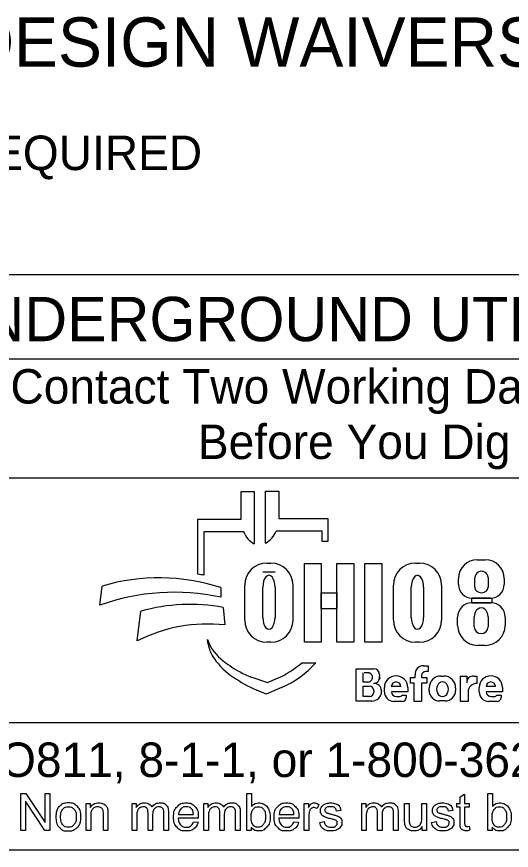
# Model space of a CAD drawing. Extents: x 0 to 34, y 0 to 22.
# Drawn here: x 2.822 to 4.831, y 2.143 to 5.529 of the extents above; entities that cross this region are included whole.
import ezdxf

# ---------------------------------------------------------------- set-up
doc = ezdxf.new("R2010")
doc.units = 0
doc.layers.add('SC_Scratch9', color=7, linetype='Continuous')
doc.layers.add('SH_Cut_Line', color=7, linetype='Continuous')

msp = doc.modelspace()

# ---------------------------------------------------------------- linework, layer by layer
at = {"layer": 'SC_Scratch9'}
for p, q in [((3.7335, 3.4883), (3.7335, 3.5998)), ((3.7335, 3.5998), (3.7872, 3.5998)), ((3.7872, 3.5998), (3.7872, 3.3877)), ((3.8329, 3.39), (3.8329, 3.6021)), ((3.8329, 3.6021), (3.8865, 3.6021)), ((3.8865, 3.6021), (3.8865, 3.4906)), ((3.5576, 3.2644), (3.5576, 3.4883)), ((3.5576, 3.4883), (3.7335, 3.4883)), ((3.8865, 3.4906), (4.0857, 3.4906)), ((4.0857, 3.4906), (4.0857, 3.3968)), ((3.5828, 3.4369), (3.5828, 3.26)), ((3.7439, 3.4369), (3.5828, 3.4369)), ((4.0625, 3.4392), (3.8761, 3.4392)), ((4.0625, 3.3968), (4.0625, 3.4392)), ((4.0857, 3.3968), (4.0625, 3.3968)), ((4.6931, 3.3231), (4.7258, 3.3231)), ((3.8385, 3.3091), (3.8551, 3.3091)), ((4.4416, 3.3091), (4.4581, 3.3091)), ((3.8718, 3.2721), (3.822, 3.2721)), ((4.683, 3.2111), (4.683, 3.2504)), ((4.7371, 3.2504), (4.7371, 3.2111)), ((3.7491, 3.0776), (3.7491, 3.2196)), ((3.9445, 3.2196), (3.9445, 3.0776)), ((4.3521, 3.0776), (4.3521, 3.2196)), ((4.5476, 3.2196), (4.5476, 3.0776)), ((4.6168, 3.2225), (4.6168, 3.2468)), ((4.8022, 3.2468), (4.8022, 3.2225)), ((3.1602, 3.1381), (3.1696, 3.2162)), ((3.6509, 3.2097), (3.6509, 3.1709)), ((3.822, 3.089), (3.822, 3.2114)), ((3.8718, 3.2114), (3.8718, 3.089)), ((4.425, 3.089), (4.425, 3.2114)), ((4.4748, 3.2114), (4.4748, 3.089)), ((4.7462, 3.1665), (4.6728, 3.1665)), ((3.6608, 3.1291), (3.6671, 3.0582)), ((4.671, 3.1482), (4.7483, 3.1482)), ((3.312, 2.9936), (3.3267, 3.1137)), ((4.6131, 3.0563), (4.6131, 3.0903)), ((4.6806, 3.0503), (4.6806, 3.0912)), ((4.7374, 3.0912), (4.7374, 3.0503)), ((4.8062, 3.0903), (4.8062, 3.0563)), ((3.5997, 2.9807), (3.5967, 2.9986)), ((3.8551, 2.9882), (3.8385, 2.9882)), ((4.4581, 2.9882), (4.4416, 2.9882)), ((4.7252, 2.9753), (4.6941, 2.9753)), ((3.98, 2.9048), (4.0375, 2.9048)), ((4.2013, 2.749), (4.2013, 2.8798)), ((4.2013, 2.8798), (4.2725, 2.8798)), ((4.4739, 2.8926), (4.4934, 2.8926)), ((4.4934, 2.8926), (4.4934, 2.8696)), ((3.7816, 2.8444), (3.841, 2.8239)), ((4.2293, 2.8263), (4.2293, 2.8632)), ((4.2545, 2.8632), (4.2332, 2.8632)), ((4.2963, 2.856), (4.2963, 2.8481)), ((4.4213, 2.8212), (4.4213, 2.8442)), ((4.4213, 2.8442), (4.4406, 2.8442)), ((4.4406, 2.8442), (4.4406, 2.8546)), ((4.4667, 2.8526), (4.4667, 2.8442)), ((4.4667, 2.8442), (4.4883, 2.8442)), ((4.4934, 2.8691), (4.4832, 2.8691)), ((4.4883, 2.8442), (4.4883, 2.8212)), ((4.5451, 2.8508), (4.5573, 2.8508)), ((4.6254, 2.7478), (4.6254, 2.8505)), ((4.6254, 2.8505), (4.6499, 2.8505)), ((4.6499, 2.8505), (4.6499, 2.8237)), ((4.6772, 2.8505), (4.691, 2.8505)), ((4.691, 2.8505), (4.691, 2.8209)), ((3.841, 2.8239), (3.8821, 2.8417)), ((4.2487, 2.8263), (4.2293, 2.8263)), ((4.4362, 2.8212), (4.4213, 2.8212)), ((4.4362, 2.7478), (4.4362, 2.8212)), ((4.4883, 2.8212), (4.4667, 2.8212)), ((4.4667, 2.8212), (4.4667, 2.7478)), ((3.835, 2.7769), (3.7976, 2.7934)), ((3.8983, 2.8044), (3.835, 2.7769)), ((4.2293, 2.7669), (4.2293, 2.8097)), ((4.2293, 2.8097), (4.2548, 2.8097)), ((4.2729, 2.7916), (4.2729, 2.7853)), ((4.3043, 2.7887), (4.3043, 2.7884)), ((4.3159, 2.7858), (4.3159, 2.8042)), ((4.3824, 2.8082), (4.3439, 2.8082)), ((4.4104, 2.7866), (4.344, 2.7866)), ((4.4104, 2.8042), (4.4104, 2.7866)), ((4.4973, 2.7922), (4.4973, 2.8029)), ((4.6051, 2.8029), (4.6051, 2.7922)), ((4.6559, 2.786), (4.6559, 2.7478)), ((4.7008, 2.7858), (4.7008, 2.8042)), ((4.7674, 2.8082), (4.7288, 2.8082)), ((4.7953, 2.7866), (4.7289, 2.7866)), ((4.7953, 2.8042), (4.7953, 2.7866)), ((4.265, 2.749), (4.2013, 2.749)), ((4.2546, 2.7669), (4.2293, 2.7669)), ((4.3892, 2.7478), (4.3538, 2.7478)), ((4.3649, 2.7673), (4.379, 2.7673)), ((4.3876, 2.7729), (4.4045, 2.7729)), ((4.4045, 2.7729), (4.4045, 2.7631)), ((4.4667, 2.7478), (4.4362, 2.7478)), ((4.5623, 2.7494), (4.5401, 2.7494)), ((4.6559, 2.7478), (4.6254, 2.7478)), ((4.7742, 2.7478), (4.7388, 2.7478)), ((4.7498, 2.7673), (4.7639, 2.7673)), ((4.7725, 2.7729), (4.7894, 2.7729)), ((4.7894, 2.7729), (4.7894, 2.7631))]:
    msp.add_line(p, q, dxfattribs=at)
for points in [[(3.991, 3.3081), (4.0589, 3.3081), (4.0589, 2.9881), (3.991, 2.9881)], [(4.1231, 3.3081), (4.1911, 3.3081), (4.1911, 2.9881), (4.1231, 2.9881)], [(4.2364, 3.3081), (4.3052, 3.3081), (4.3052, 2.9881), (4.2364, 2.9881)], [(4.0589, 3.1882), (4.1231, 3.1882), (4.1231, 3.1242), (4.0589, 3.1242)], [(4.6706, 3.1665), (4.7523, 3.1665), (4.7523, 3.1481), (4.6706, 3.1481)]]:
    msp.add_lwpolyline(points, close=True, dxfattribs=at)
for points in [[(2.8389, 2.2239), (2.8389, 2.3741), (2.8592, 2.3741), (2.9382, 2.2561), (2.9382, 2.3741), (2.9572, 2.3741), (2.9572, 2.2239), (2.9369, 2.2239), (2.8579, 2.3419), (2.8579, 2.2239), (2.8389, 2.2239)], [(3.7743, 2.2239), (3.7573, 2.2239), (3.7573, 2.3741), (3.7757, 2.3741), (3.7757, 2.3206)], [(4.6233, 2.2558), (4.6233, 2.3185), (4.6097, 2.3185), (4.6097, 2.3328), (4.6233, 2.3328), (4.6233, 2.3597), (4.6417, 2.3708), (4.6417, 2.3328), (4.6601, 2.3328), (4.6601, 2.3185), (4.6417, 2.3185), (4.6417, 2.2547)], [(4.7534, 2.2239), (4.7363, 2.2239), (4.7363, 2.3741), (4.7548, 2.3741), (4.7548, 2.3206)], [(3.1048, 2.2239), (3.1048, 2.3328), (3.1214, 2.3328), (3.1214, 2.3173)], [(3.2912, 2.2239), (3.2912, 2.3328), (3.3077, 2.3328), (3.3077, 2.3174)], [(3.5826, 2.2239), (3.5826, 2.3328), (3.5991, 2.3328), (3.5991, 2.3174)], [(3.9904, 2.2239), (3.9904, 2.3328), (4.007, 2.3328), (4.007, 2.3163)], [(4.0495, 2.3293), (4.043, 2.3122)], [(4.1394, 2.3046), (4.1213, 2.3022)], [(4.2236, 2.2239), (4.2236, 2.3328), (4.2401, 2.3328), (4.2401, 2.3174)], [(4.3979, 2.2654), (4.3979, 2.3328), (4.4164, 2.3328), (4.4164, 2.2724)], [(4.4676, 2.2745), (4.4676, 2.3328), (4.4861, 2.3328), (4.4861, 2.2239), (4.4696, 2.2239)], [(4.594, 2.3046), (4.5759, 2.3022)], [(3.1233, 2.2833), (3.1233, 2.2239), (3.1048, 2.2239)], [(3.1932, 2.2908), (3.1932, 2.2239), (3.1748, 2.2239), (3.1748, 2.2901)], [(3.3097, 2.2803), (3.3097, 2.2239), (3.2912, 2.2239)], [(3.3743, 2.2871), (3.3743, 2.2239), (3.3559, 2.2239), (3.3559, 2.2946)], [(3.4388, 2.2986), (3.4388, 2.2239), (3.4203, 2.2239), (3.4203, 2.2924)], [(3.56, 2.2736), (3.4788, 2.2736)], [(3.4799, 2.2887), (3.5406, 2.2887)], [(3.601, 2.2803), (3.601, 2.2239), (3.5826, 2.2239)], [(3.6657, 2.2871), (3.6657, 2.2239), (3.6473, 2.2239), (3.6473, 2.2946)], [(3.7301, 2.2986), (3.7301, 2.2239), (3.7117, 2.2239), (3.7117, 2.2924)], [(3.968, 2.2736), (3.8868, 2.2736)], [(3.8879, 2.2887), (3.9486, 2.2887)], [(4.0088, 2.2809), (4.0088, 2.2239), (3.9904, 2.2239)], [(4.242, 2.2803), (4.242, 2.2239), (4.2236, 2.2239)], [(4.3067, 2.2871), (4.3067, 2.2239), (4.2883, 2.2239), (4.2883, 2.2946)], [(4.3711, 2.2986), (4.3711, 2.2239), (4.3527, 2.2239), (4.3527, 2.2924)], [(3.5404, 2.2591), (3.5595, 2.2567)], [(3.7743, 2.2375), (3.7743, 2.2239)], [(3.9484, 2.2591), (3.9675, 2.2567)], [(4.053, 2.2564), (4.0712, 2.2593)], [(4.4696, 2.2239), (4.4696, 2.24)], [(4.5076, 2.2564), (4.5258, 2.2593)], [(4.6601, 2.2404), (4.6628, 2.2241)], [(4.7534, 2.2375), (4.7534, 2.2239)]]:
    msp.add_lwpolyline(points, dxfattribs=at)
for centre, radius, start, end in [((3.8353, 3.4736), 0.0985, 201.9296, 240.7469), ((3.7847, 3.476), 0.0985, 299.2531, 338.0704), ((4.6931, 3.2468), 0.0763, 90, 180), ((4.7258, 3.2468), 0.0763, 0, 90), ((3.8385, 3.2196), 0.0895, 90, 180), ((3.8551, 3.2196), 0.0895, 0, 90), ((4.4416, 3.2196), 0.0895, 90, 180), ((4.4581, 3.2196), 0.0895, 0, 90), ((3.4295, 2.4554), 0.8191, 79.2074, 81.0007), ((3.3997, 2.4302), 0.8191, 72.1402, 106.3144), ((4.6728, 3.2225), 0.056, 180, 270), ((4.7462, 3.2225), 0.056, 270, 0), ((3.4628, 2.2991), 0.8919, 77.8238, 109.8274), ((3.5267, 2.4094), 0.7322, 79.44, 105.8467), ((4.671, 3.0903), 0.0579, 90, 180), ((4.7483, 3.0903), 0.0579, 0, 90), ((3.5987, 2.4262), 0.6357, 83.8248, 116.8021), ((3.8385, 3.0776), 0.0895, 180, 270), ((3.8551, 3.0776), 0.0895, 270, 0), ((4.4416, 3.0776), 0.0895, 180, 270), ((4.4581, 3.0776), 0.0895, 270, 0), ((4.6941, 3.0563), 0.081, 180, 270), ((4.7252, 3.0563), 0.081, 270, 0), ((3.7841, 3.0707), 0.2008, 201.0457, 232.5314), ((3.741, 3.0048), 0.1433, 189.6817, 216.0884), ((3.8747, 3.1022), 0.3088, 216.0884, 235.7167), ((3.9766, 3.3219), 0.5173, 232.5314, 241.794), ((3.7387, 3.1722), 0.3602, 293.4582, 312.0712), ((3.7387, 3.1722), 0.401, 293.4582, 317.8286), ((4.2725, 2.856), 0.0238, 0, 90), ((4.4739, 2.859), 0.0335, 90, 187.5187), ((4.0412, 3.3465), 0.6044, 235.7167, 246.2325), ((3.8914, 3.1631), 0.3371, 241.794, 250.9821), ((4.2487, 2.845), 0.0187, 270, 2.0582), ((4.2505, 2.8463), 0.0169, 357.8325, 90), ((4.2721, 2.8453), 0.0243, 270, 6.6529), ((4.3631, 2.8042), 0.0473, 0, 180), ((4.4832, 2.8526), 0.0165, 90, 180), ((4.5451, 2.8029), 0.0478, 90, 180), ((4.5573, 2.8029), 0.0478, 0, 90), ((4.6768, 2.8237), 0.0269, 89.2449, 180), ((4.7481, 2.8042), 0.0473, 0, 180), ((4.2722, 2.7889), 0.0321, 4.0748, 90), ((4.2827, 2.8438), 0.0175, 347.4023, 0), ((4.3632, 2.8072), 0.0193, 2.9632, 177.0368), ((4.6908, 2.786), 0.0349, 89.6033, 180), ((4.7481, 2.8072), 0.0193, 2.9632, 177.0368), ((4.2546, 2.7853), 0.0184, 270, 0), ((4.2548, 2.7916), 0.0181, 0, 90), ((4.265, 2.7884), 0.0393, 270, 0), ((4.2714, 2.7887), 0.033, 0, 11.7502), ((4.3538, 2.7858), 0.038, 180, 270), ((4.3649, 2.7883), 0.021, 184.827, 270), ((4.5401, 2.7922), 0.0428, 180, 270), ((4.5623, 2.7922), 0.0428, 270, 0), ((4.7388, 2.7858), 0.038, 180, 270), ((4.7498, 2.7883), 0.021, 184.827, 270), ((4.379, 2.7767), 0.00938, 270, 335.9979), ((4.3892, 2.7631), 0.0152, 270, 0), ((4.7639, 2.7767), 0.00938, 270, 335.9979), ((4.7742, 2.7631), 0.0152, 270, 0)]:
    msp.add_arc(centre, radius, start, end, dxfattribs=at)
for centre, major_axis, ratio, start_param, end_param in [((3.8469, 3.2114), (0, 0.0484), 0.514403, 4.712389, 7.853982), ((4.4499, 3.2114), (0, 0.0484), 0.514403, 4.712389, 7.853982), ((4.71, 3.2504), (0.0271, 0), 0.969373, 0, 3.141593), ((4.71, 3.2111), (0.0271, 0), 0.818453, 3.141593, 6.283185), ((4.709, 3.0912), (0, 0.0358), 0.794529, 4.712389, 7.853982), ((3.8469, 3.089), (0, 0.0484), 0.514403, 1.570796, 4.712389), ((4.4499, 3.089), (0, 0.0484), 0.514403, 1.570796, 4.712389), ((4.709, 3.0503), (0.0284, 0), 0.959837, 3.141593, 6.283185), ((4.5517, 2.7976), (0, 0.029), 0.832186, 4.712389, 7.853982), ((4.5517, 2.7976), (0, 0.0302), 0.797287, 1.570796, 4.712389)]:
    msp.add_ellipse(centre, major_axis=major_axis, ratio=ratio, start_param=start_param, end_param=end_param, dxfattribs=at)
for points in [[(2.9814, 2.2783), (2.9814, 2.3085), (2.9981, 2.3231), (3.0122, 2.3352), (3.0323, 2.3352), (3.0547, 2.3352), (3.069, 2.3205), (3.0832, 2.3058), (3.0832, 2.2799), (3.0832, 2.2589), (3.0769, 2.2469), (3.0706, 2.2348), (3.0586, 2.2282), (3.0466, 2.2215), (3.0323, 2.2215), (3.0095, 2.2215), (2.9954, 2.2362), (2.9814, 2.2508), (2.9814, 2.2783)], [(3.0003, 2.2783), (3.0003, 2.2574), (3.0094, 2.247), (3.0185, 2.2366), (3.0323, 2.2366), (3.046, 2.2366), (3.0551, 2.2471), (3.0642, 2.2575), (3.0642, 2.279), (3.0642, 2.2991), (3.0551, 2.3095), (3.0459, 2.3199), (3.0323, 2.3199), (3.0185, 2.3199), (3.0094, 2.3096), (3.0003, 2.2992), (3.0003, 2.2783)], [(3.1214, 2.3173), (3.1334, 2.3352), (3.156, 2.3352), (3.1659, 2.3352), (3.1741, 2.3316), (3.1823, 2.3281), (3.1864, 2.3224), (3.1905, 2.3166), (3.1922, 2.3087), (3.1932, 2.3036), (3.1932, 2.2908)], [(3.1748, 2.2901), (3.1748, 2.3013), (3.1726, 2.3069), (3.1705, 2.3125), (3.165, 2.3158), (3.1595, 2.3191), (3.1521, 2.3191), (3.1404, 2.3191), (3.1318, 2.3117), (3.1233, 2.3042), (3.1233, 2.2833)], [(3.3077, 2.3174), (3.3128, 2.3254), (3.3214, 2.3303), (3.3299, 2.3352), (3.3407, 2.3352), (3.3528, 2.3352), (3.3606, 2.3301), (3.3683, 2.3251), (3.3715, 2.3161), (3.3844, 2.3352), (3.4051, 2.3352), (3.4213, 2.3352), (3.43, 2.3262), (3.4388, 2.3172), (3.4388, 2.2986)], [(3.3559, 2.2946), (3.3559, 2.3069), (3.3514, 2.313), (3.3469, 2.3191), (3.3366, 2.3191), (3.3288, 2.3191), (3.3222, 2.315), (3.3156, 2.311), (3.3126, 2.3031), (3.3097, 2.2952), (3.3097, 2.2803)], [(3.4203, 2.2924), (3.4203, 2.3035), (3.4185, 2.3083), (3.4168, 2.3132), (3.412, 2.3162), (3.4073, 2.3191), (3.401, 2.3191), (3.3895, 2.3191), (3.3819, 2.3115), (3.3743, 2.3039), (3.3743, 2.2871)], [(3.5595, 2.2567), (3.555, 2.24), (3.5428, 2.2307), (3.5306, 2.2215), (3.5117, 2.2215), (3.4878, 2.2215), (3.4738, 2.2362), (3.4598, 2.2509), (3.4598, 2.2774), (3.4598, 2.3049), (3.474, 2.32), (3.4881, 2.3352), (3.5106, 2.3352), (3.5324, 2.3352), (3.5463, 2.3203), (3.5601, 2.3055), (3.5601, 2.2785), (3.5601, 2.2769), (3.56, 2.2736)], [(3.5406, 2.2887), (3.5394, 2.3025), (3.5337, 2.3094), (3.5249, 2.3201), (3.5108, 2.3201), (3.4981, 2.3201), (3.4894, 2.3115), (3.4808, 2.303), (3.4799, 2.2887)], [(3.5991, 2.3174), (3.6042, 2.3254), (3.6127, 2.3303), (3.6212, 2.3352), (3.6321, 2.3352), (3.6442, 2.3352), (3.6519, 2.3301), (3.6597, 2.3251), (3.6628, 2.3161), (3.6758, 2.3352), (3.6965, 2.3352), (3.7127, 2.3352), (3.7214, 2.3262), (3.7301, 2.3172), (3.7301, 2.2986)], [(3.6473, 2.2946), (3.6473, 2.3069), (3.6428, 2.313), (3.6383, 2.3191), (3.628, 2.3191), (3.6202, 2.3191), (3.6136, 2.315), (3.607, 2.311), (3.604, 2.3031), (3.601, 2.2952), (3.601, 2.2803)], [(3.7117, 2.2924), (3.7117, 2.3035), (3.7099, 2.3083), (3.7081, 2.3132), (3.7034, 2.3162), (3.6987, 2.3191), (3.6923, 2.3191), (3.6809, 2.3191), (3.6733, 2.3115), (3.6657, 2.3039), (3.6657, 2.2871)], [(3.7741, 2.2792), (3.7741, 2.2596), (3.7794, 2.2509), (3.7881, 2.2366), (3.8029, 2.2366), (3.815, 2.2366), (3.8238, 2.2471), (3.8326, 2.2576), (3.8326, 2.2784), (3.8326, 2.2998), (3.8241, 2.3099), (3.8157, 2.3201), (3.8038, 2.3201), (3.7917, 2.3201), (3.7829, 2.3096), (3.7741, 2.299), (3.7741, 2.2792)], [(3.7757, 2.3206), (3.7874, 2.3352), (3.8055, 2.3352), (3.8155, 2.3352), (3.8245, 2.3311), (3.8335, 2.3271), (3.8392, 2.3198), (3.845, 2.3124), (3.8483, 2.3021), (3.8516, 2.2918), (3.8516, 2.28), (3.8516, 2.252), (3.8378, 2.2368), (3.8239, 2.2215), (3.8046, 2.2215), (3.7853, 2.2215), (3.7743, 2.2375)], [(3.9675, 2.2567), (3.963, 2.24), (3.9508, 2.2307), (3.9386, 2.2215), (3.9196, 2.2215), (3.8958, 2.2215), (3.8818, 2.2362), (3.8678, 2.2509), (3.8678, 2.2774), (3.8678, 2.3049), (3.882, 2.32), (3.8961, 2.3352), (3.9186, 2.3352), (3.9404, 2.3352), (3.9543, 2.3203), (3.9681, 2.3055), (3.9681, 2.2785), (3.9681, 2.2769), (3.968, 2.2736)], [(3.9486, 2.2887), (3.9474, 2.3025), (3.9417, 2.3094), (3.9328, 2.3201), (3.9188, 2.3201), (3.9061, 2.3201), (3.8974, 2.3115), (3.8888, 2.303), (3.8879, 2.2887)], [(4.007, 2.3163), (4.0133, 2.3278), (4.0187, 2.3315), (4.0241, 2.3352), (4.0305, 2.3352), (4.0398, 2.3352), (4.0495, 2.3293)], [(4.043, 2.3122), (4.0363, 2.3162), (4.0295, 2.3162), (4.0235, 2.3162), (4.0187, 2.3125), (4.0139, 2.3089), (4.0119, 2.3024), (4.0088, 2.2926), (4.0088, 2.2809)], [(4.1213, 2.3022), (4.1201, 2.3106), (4.1142, 2.3153), (4.1083, 2.3201), (4.0975, 2.3201), (4.0848, 2.3201), (4.0794, 2.3159), (4.0739, 2.3116), (4.0739, 2.306), (4.0739, 2.3024), (4.0762, 2.2995), (4.0785, 2.2966), (4.0833, 2.2946), (4.086, 2.2936), (4.0996, 2.2899), (4.1192, 2.2847), (4.1269, 2.2813), (4.1347, 2.278), (4.1391, 2.2717), (4.1435, 2.2653), (4.1435, 2.2559), (4.1435, 2.2467), (4.1381, 2.2386), (4.1327, 2.2304), (4.1226, 2.226), (4.1124, 2.2215), (4.0996, 2.2215), (4.0784, 2.2215), (4.0672, 2.2303), (4.0561, 2.2391), (4.053, 2.2564)], [(4.0712, 2.2593), (4.0727, 2.2483), (4.0798, 2.2425), (4.0868, 2.2366), (4.0995, 2.2366), (4.1122, 2.2366), (4.1184, 2.2418), (4.1245, 2.247), (4.1245, 2.254), (4.1245, 2.2602), (4.1191, 2.2638), (4.1153, 2.2663), (4.1002, 2.2701), (4.0799, 2.2752), (4.072, 2.2789), (4.0642, 2.2827), (4.0601, 2.2893), (4.0561, 2.2959), (4.0561, 2.3038), (4.0561, 2.3111), (4.0594, 2.3173), (4.0628, 2.3235), (4.0685, 2.3276), (4.0728, 2.3308), (4.0803, 2.333), (4.0877, 2.3352), (4.0962, 2.3352), (4.109, 2.3352), (4.1187, 2.3315), (4.1284, 2.3278), (4.133, 2.3215), (4.1377, 2.3152), (4.1394, 2.3046)], [(4.2401, 2.3174), (4.2452, 2.3254), (4.2537, 2.3303), (4.2622, 2.3352), (4.2731, 2.3352), (4.2852, 2.3352), (4.2929, 2.3301), (4.3007, 2.3251), (4.3038, 2.3161), (4.3168, 2.3352), (4.3375, 2.3352), (4.3537, 2.3352), (4.3624, 2.3262), (4.3711, 2.3172), (4.3711, 2.2986)], [(4.2883, 2.2946), (4.2883, 2.3069), (4.2838, 2.313), (4.2793, 2.3191), (4.269, 2.3191), (4.2612, 2.3191), (4.2546, 2.315), (4.248, 2.311), (4.245, 2.3031), (4.242, 2.2952), (4.242, 2.2803)], [(4.3527, 2.2924), (4.3527, 2.3035), (4.3509, 2.3083), (4.3491, 2.3132), (4.3444, 2.3162), (4.3397, 2.3191), (4.3333, 2.3191), (4.3219, 2.3191), (4.3143, 2.3115), (4.3067, 2.3039), (4.3067, 2.2871)], [(4.5759, 2.3022), (4.5747, 2.3106), (4.5688, 2.3153), (4.5629, 2.3201), (4.5521, 2.3201), (4.5394, 2.3201), (4.5339, 2.3159), (4.5285, 2.3116), (4.5285, 2.306), (4.5285, 2.3024), (4.5308, 2.2995), (4.533, 2.2966), (4.5378, 2.2946), (4.5406, 2.2936), (4.5542, 2.2899), (4.5737, 2.2847), (4.5815, 2.2813), (4.5893, 2.278), (4.5937, 2.2717), (4.5981, 2.2653), (4.5981, 2.2559), (4.5981, 2.2467), (4.5927, 2.2386), (4.5873, 2.2304), (4.5772, 2.226), (4.567, 2.2215), (4.5542, 2.2215), (4.5329, 2.2215), (4.5218, 2.2303), (4.5107, 2.2391), (4.5076, 2.2564)], [(4.5258, 2.2593), (4.5273, 2.2483), (4.5343, 2.2425), (4.5414, 2.2366), (4.554, 2.2366), (4.5668, 2.2366), (4.5729, 2.2418), (4.5791, 2.247), (4.5791, 2.254), (4.5791, 2.2602), (4.5736, 2.2638), (4.5698, 2.2663), (4.5548, 2.2701), (4.5345, 2.2752), (4.5266, 2.2789), (4.5188, 2.2827), (4.5147, 2.2893), (4.5107, 2.2959), (4.5107, 2.3038), (4.5107, 2.3111), (4.514, 2.3173), (4.5173, 2.3235), (4.5231, 2.3276), (4.5274, 2.3308), (4.5348, 2.333), (4.5423, 2.3352), (4.5508, 2.3352), (4.5636, 2.3352), (4.5733, 2.3315), (4.583, 2.3278), (4.5876, 2.3215), (4.5922, 2.3152), (4.594, 2.3046)], [(4.7532, 2.2792), (4.7532, 2.2596), (4.7585, 2.2509), (4.7672, 2.2366), (4.782, 2.2366), (4.7941, 2.2366), (4.8029, 2.2471), (4.8116, 2.2576), (4.8116, 2.2784), (4.8116, 2.2998), (4.8032, 2.3099), (4.7948, 2.3201), (4.7828, 2.3201), (4.7708, 2.3201), (4.762, 2.3096), (4.7532, 2.299), (4.7532, 2.2792)], [(4.7548, 2.3206), (4.7664, 2.3352), (4.7846, 2.3352), (4.7946, 2.3352), (4.8036, 2.3311), (4.8125, 2.3271), (4.8183, 2.3198), (4.8241, 2.3124), (4.8274, 2.3021), (4.8306, 2.2918), (4.8306, 2.28), (4.8306, 2.252), (4.8168, 2.2368), (4.803, 2.2215), (4.7836, 2.2215), (4.7644, 2.2215), (4.7534, 2.2375)], [(3.4788, 2.2736), (3.4799, 2.2557), (3.489, 2.2462), (3.4981, 2.2366), (3.5117, 2.2366), (3.5219, 2.2366), (3.5291, 2.242), (3.5362, 2.2473), (3.5404, 2.2591)], [(3.8868, 2.2736), (3.8879, 2.2557), (3.897, 2.2462), (3.9061, 2.2366), (3.9197, 2.2366), (3.9299, 2.2366), (3.937, 2.242), (3.9442, 2.2473), (3.9484, 2.2591)], [(4.4164, 2.2724), (4.4164, 2.258), (4.4175, 2.253), (4.4192, 2.2457), (4.4249, 2.2416), (4.4305, 2.2374), (4.4388, 2.2374), (4.4471, 2.2374), (4.4543, 2.2417), (4.4616, 2.2459), (4.4646, 2.2533), (4.4676, 2.2606), (4.4676, 2.2745)], [(4.4696, 2.24), (4.4569, 2.2215), (4.4351, 2.2215), (4.4255, 2.2215), (4.4171, 2.2252), (4.4088, 2.2289), (4.4047, 2.2345), (4.4007, 2.2401), (4.3991, 2.2482), (4.3979, 2.2536), (4.3979, 2.2654)], [(4.6628, 2.2241), (4.655, 2.2224), (4.6488, 2.2224), (4.6388, 2.2224), (4.6333, 2.2256), (4.6278, 2.2288), (4.6255, 2.234), (4.6233, 2.2392), (4.6233, 2.2558)], [(4.6417, 2.2547), (4.6417, 2.2468), (4.6427, 2.2445), (4.6436, 2.2423), (4.6458, 2.2409), (4.648, 2.2396), (4.6521, 2.2396), (4.6551, 2.2396), (4.6601, 2.2404)]]:
    msp.add_open_spline(points, degree=3, dxfattribs=at)
at = {"layer": 'SH_Cut_Line'}
for p, q in [((6.6275, 4.4803), (2.3775, 4.4803)), ((2.3775, 4.1387), (6.6275, 4.1387)), ((2.3775, 3.6553), (6.6275, 3.6553)), ((6.6275, 2.6607), (2.3775, 2.6607)), ((6.6275, 2.1428), (2.3775, 2.1428))]:
    msp.add_line(p, q, dxfattribs=at)

# ---------------------------------------------------------------- texts
at = {"layer": 'SC_Scratch9'}
for s, height, p in [('ADA DESIGN WAIVERS', 0.2, (1.9944, 5.3256)), ('NONE REQUIRED', 0.14, (1.9944, 4.9056)), ('UNDERGROUND UTILITIES', 0.18, (2.5057, 4.2106)), ('Contact Two Working Days', 0.14, (2.7972, 3.9571)), ('Before You Dig', 0.14, (3.5583, 3.7321)), ('OHIO811, 8-1-1, or 1-800-362-2764', 0.14, (2.422, 2.4406))]:
    msp.add_text(s, height=height, dxfattribs=at).set_placement(p)

doc.saveas('drawing.dxf')
